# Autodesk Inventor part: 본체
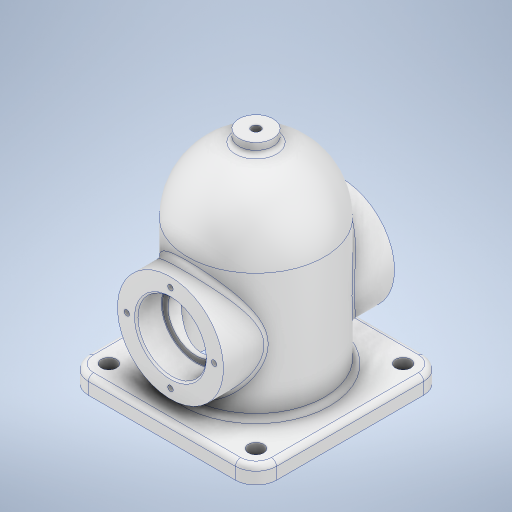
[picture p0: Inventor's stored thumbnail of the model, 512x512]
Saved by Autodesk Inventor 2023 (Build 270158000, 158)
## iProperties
Created: 2025-04
Part Number: 본체
Material: 알루미늄 6061
Document SubType Name: Modeling
Designer: user
Density: 2.7 g/cm^3
Appearance: 알루미늄 - 평지
Mass: 865.841 g
Surface Area: 799.536 cm^2
Volume: 320.682 cm^3
Author: user
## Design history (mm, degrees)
sketch "스케치1"
  geometry: L1 (-40, 0)-(-40, -84); L2 (-40, -84)-(0, -84); L3 (-57.941, 0)-(9.657, 0) reference; L4 (0, -110.457)-(0, 74.741) reference; L5 (0, 40)-(0, -84); A1 r 40 centre (0, 0) between (0, 40) and (-40, 0); 1 further point
  constraints: 6 end point, 3 point on line, 2 point on circle, 1 centre point, 1 coincident, 1 collinear, 1 perpendicular, 1 tangent, 1 vertical
  dimensions: "d0" = 80 diameter of A1; "d1" = 84 distance from line of L2 point (0, 0)
revolve "회전1" sketch "스케치1" stored, may be unused: angle "d2" = 90 deg
node "작업 평면1"
sketch "스케치2"
  geometry: L1 (55, -55)-(-55, -55); L2 (-55, -55)-(-55, 55); L3 (-55, 55)-(55, 55); L4 (55, 55)-(55, -55); L5 (55, -55)-(-55, 55); L6 (-55, -55)-(55, 55); 1 further point
  constraints: 12 end point, 2 midpoint, 2 parallel, 1 horizontal, 1 perpendicular
  dimensions: "d4" = 110 distance of L1.start L1.end; "d5" = 110 distance of L1.end L2.end
extrude "돌출1" join sketch "스케치2" distance "d6" = 10; taper "d7" = 0 deg
node "작업 평면2"
sketch "스케치3"
  geometry: C1 r 10 at (55, -55); 1 further point
  constraints: 1 centre point, 1 coincident
  dimensions: "d9" = 20 diameter of C1
extrude "돌출2" join sketch "스케치3" stored distance "d10" = 10; taper "d11" = 0 deg
sketch "스케치4"
  geometry: L1 (-84, -55)-(-84, 55) reference; L2 (32, 0)-(-32, 0); L3 (0, 32)-(-84, 32); L4 (-84, 32)-(-84, 0); L5 (-84, 0)-(-32, 0); L6 (-74, 40)-(0, 40) reference; A1 r 32 centre (0, 0) between (32, 0) and (0, 32); 3 further points
  constraints: 8 end point, 2 horizontal, 2 perpendicular, 2 point on circle, 1 centre point, 1 coincident, 1 collinear, 1 horizontal alignment, 1 tangent
  dimensions: "d12" = 64 diameter of A1
revolve "회전2" sketch "스케치4" stored, may be unused: angle "d13" = 90 deg
node "작업 평면3"
sketch "스케치5"
  geometry: L1 (-55, -84)-(55, -84) reference; C1 r 31 at (0, -36); 1 further point
  constraints: 1 centre point, 1 vertical alignment
  dimensions: "d15" = 48 distance from line of L1 C1.centre; "d16" = 62 diameter of C1
extrude "돌출3" join sketch "스케치5" stored distance "d17" = 10; taper "d18" = 0 deg
sketch "스케치6"
  geometry: C1 r 20 at (0, 0); C2 r 31 at (0, 0) reference; 1 further point
  constraints: 1 centre point, 1 concentric
  dimensions: "d19" = 40 diameter of C1
extrude "돌출4" cut sketch "스케치6" distance "d20" = 15; taper "d21" = 0 deg
sketch "스케치7"
  geometry: C1 r 16.5 at (0, 0); C2 r 20 at (0, 0) reference; 1 further point
  constraints: 1 centre point, 1 concentric
  dimensions: "d22" = 33 diameter of C1
extrude "돌출5" cut sketch "스케치7" extent not by distance; stored distance "d23" = 0; taper "d24" = 0 deg
sketch "스케치8" dims "d25" = 51
  geometry: C1 r 31 at (0, 0) reference; 3 further points
  constraints: 2 vertical alignment, 3 other
hole "구멍1" sketch "스케치8" at (0, 25.5) diameter "d26" = 3.242; stored, may be unused: countersink angle "d30" = 90 deg, drill point angle "d32" = 118 deg; dims "d27" = 8, "d28" = 4, "d29" = 2, "d31" = 10
sketch "스케치9"
  geometry: 2 further points
  constraints: 1 coincident
hole "구멍2" sketch "스케치9" at (0, 0) diameter "d36" = 5.1881; stored, may be unused: countersink angle "d40" = 90 deg, drill point angle "d42" = 0 deg; dims "d37" = 12, "d38" = 4, "d39" = 2, "d41" = 16
fillet "모깎기1" dims "d43" = 12
sketch "스케치10"
  geometry: C1 r 4.5 at (43, -43); C2 r 4.5 at (-43, -43); C3 r 4.5 at (-43, 43); C4 r 4.5 at (43, 43); A1 r 12 centre (43, -43) between (43, -55) and (55, -43) reference; A2 r 12 centre (-43, -43) between (-55, -43) and (-43, -55) reference; A3 r 12 centre (-43, 43) between (-43, 55) and (-55, 43) reference; A4 r 12 centre (43, 43) between (55, 43) and (43, 55) reference; 1 further point
  constraints: 4 centre point, 4 coincident, 3 equal radius
  dimensions: "d44" = 9 diameter of C1
extrude "돌출6" cut sketch "스케치10" distance "d45" = 10; taper "d46" = 0 deg
chamfer "모따기1" distance "d47" = 1; stored, may be unused: second distance "d48" = 2, angle "d49" = 45 deg
fillet "모깎기2" dims "d50" = 0.3
fillet "모깎기3" dims "d51" = 3
node "작업 평면4"
sketch "스케치12"
  geometry: L1 (84, -43)-(84, 43) reference; 2 further points
  constraints: 1 horizontal alignment, 1 other
  dimensions: "d53" = 30 distance from line of L1 point (54, 0)
feature "엠보싱1" sketch "스케치12" dims "d0" = 80, "d1" = 84, "d54" = 0.5, "d55" = 0
feature "̀耀̂耀̄耀̆耀̈耀̊耀̌耀̎耀" dims "d0" = 80, "d1" = 84, "d2" = 90 deg, "d3" = -84, "d4" = 110, "d5" = 110, "d6" = 10, "d7" = 0, "d8" = -129, "d9" = 20, "d10" = 10, "d11" = 0, "d12" = 64, "d13" = 90 deg, "d14" = 50, "d15" = 48, "d16" = 62, "d17" = 10, "d18" = 0, "d19" = 40, "d20" = 15, "d21" = 0, "d22" = 33, "d23" = 0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
node "솔리드1"
mirror "미러1"
mirror "미러2"
pattern_circular "원형 패턴1" dims angle "d34" = 360 deg
mirror "미러3"
feature "A9D066F2-1C7D-4E18-AEED-F7BC21143FA4" dims "d26" = 3.242, "d27" = 8, "d28" = 4, "d29" = 2, "d30" = 90 deg, "d31" = 10, "d32" = 118 deg
